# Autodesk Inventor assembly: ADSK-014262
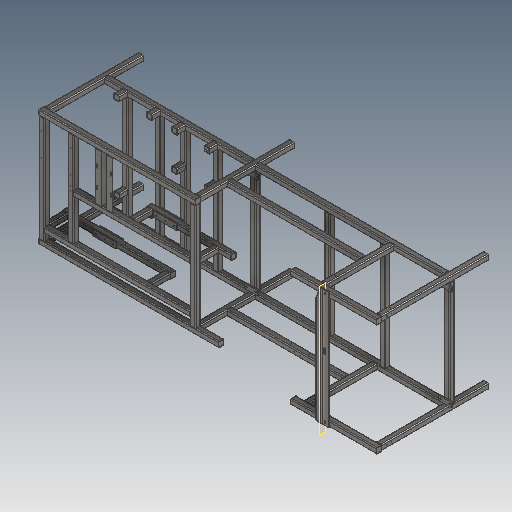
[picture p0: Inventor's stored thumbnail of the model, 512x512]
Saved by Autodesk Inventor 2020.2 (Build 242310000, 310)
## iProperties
Part Number: ADSK-014262
Description: Phantom-Baugruppe
Document SubType Name: Baugruppe
Designer: lutzd
Mass: 247578 g
Surface Area: 122547 cm^2
Volume: 31538.6 cm^3
Density: 7.85 g/cm^3
DocNumber: ADSK-014262
Folder: .
Dimensions: 1030x1037x3112,5 mm
Mass: 247,578 kg
_FrameDoc: Frame Assembly
_Version: 15.0.0
Title: Gestellbaugruppen
Author: lutzd
Revision Number: -
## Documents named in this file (57)
- D:\07 - DEMODATEN\OTX 2019 - Dataset - UPDATE - Dez2019\Designs\07-Packing machine\ADSK-014261\Frame\ADSK-014262.iam
- D:\07 - DEMODATEN\OTX 2019 - Dataset - UPDATE - Dez2019\Designs\07-Packing machine\ADSK-014261\Frame\ADSK-014267.ipt
- D:\07 - DEMODATEN\OTX 2019 - Dataset - UPDATE - Dez2019\Designs\07-Packing machine\ADSK-014261\Frame\ADSK-014265.ipt
- D:\07 - DEMODATEN\OTX 2019 - Dataset - UPDATE - Dez2019\Designs\07-Packing machine\ADSK-014261\Frame\ADSK-014264.ipt
- D:\07 - DEMODATEN\OTX 2019 - Dataset - UPDATE - Dez2019\Designs\07-Packing machine\ADSK-014261\Frame\ADSK-014263.ipt
- D:\07 - DEMODATEN\OTX 2019 - Dataset - UPDATE - Dez2019\Designs\07-Packing machine\ADSK-014261\Frame\ADSK-014280.ipt
- D:\07 - DEMODATEN\OTX 2019 - Dataset - UPDATE - Dez2019\Designs\07-Packing machine\ADSK-014261\Frame\ADSK-014279.ipt
- D:\07 - DEMODATEN\OTX 2019 - Dataset - UPDATE - Dez2019\Designs\07-Packing machine\ADSK-014261\Frame\ADSK-014278.ipt
- D:\07 - DEMODATEN\OTX 2019 - Dataset - UPDATE - Dez2019\Designs\07-Packing machine\ADSK-014261\Frame\ADSK-014276.ipt
- D:\07 - DEMODATEN\OTX 2019 - Dataset - UPDATE - Dez2019\Designs\07-Packing machine\ADSK-014261\Frame\ADSK-014275.ipt
- D:\07 - DEMODATEN\OTX 2019 - Dataset - UPDATE - Dez2019\Designs\07-Packing machine\ADSK-014261\Frame\ADSK-014274.ipt
- D:\07 - DEMODATEN\OTX 2019 - Dataset - UPDATE - Dez2019\Designs\07-Packing machine\ADSK-014261\Frame\ADSK-014273.ipt
- D:\07 - DEMODATEN\OTX 2019 - Dataset - UPDATE - Dez2019\Designs\07-Packing machine\ADSK-014261\Frame\ADSK-014272.ipt
- D:\07 - DEMODATEN\OTX 2019 - Dataset - UPDATE - Dez2019\Designs\07-Packing machine\ADSK-014261\Frame\ADSK-014271.ipt
- D:\07 - DEMODATEN\OTX 2019 - Dataset - UPDATE - Dez2019\Designs\07-Packing machine\ADSK-014261\Frame\ADSK-014270.ipt
- D:\07 - DEMODATEN\OTX 2019 - Dataset - UPDATE - Dez2019\Designs\07-Packing machine\ADSK-014261\Frame\ADSK-014269.ipt
- D:\07 - DEMODATEN\OTX 2019 - Dataset - UPDATE - Dez2019\Designs\07-Packing machine\ADSK-014261\Frame\ADSK-014268.ipt
- D:\07 - DEMODATEN\OTX 2019 - Dataset - UPDATE - Dez2019\Designs\07-Packing machine\ADSK-014261\Frame\ADSK-014304.ipt
- D:\07 - DEMODATEN\OTX 2019 - Dataset - UPDATE - Dez2019\Designs\07-Packing machine\ADSK-014261\Frame\ADSK-014303.ipt
- D:\07 - DEMODATEN\OTX 2019 - Dataset - UPDATE - Dez2019\Designs\07-Packing machine\ADSK-014261\Frame\ADSK-014302.ipt
- D:\07 - DEMODATEN\OTX 2019 - Dataset - UPDATE - Dez2019\Designs\07-Packing machine\ADSK-014261\Frame\ADSK-014301.ipt
- D:\07 - DEMODATEN\OTX 2019 - Dataset - UPDATE - Dez2019\Designs\07-Packing machine\ADSK-014261\Frame\ADSK-014300.ipt
- D:\07 - DEMODATEN\OTX 2019 - Dataset - UPDATE - Dez2019\Designs\07-Packing machine\ADSK-014261\Frame\ADSK-014299.ipt
- D:\07 - DEMODATEN\OTX 2019 - Dataset - UPDATE - Dez2019\Designs\07-Packing machine\ADSK-014261\Frame\ADSK-014298.ipt
- D:\07 - DEMODATEN\OTX 2019 - Dataset - UPDATE - Dez2019\Designs\07-Packing machine\ADSK-014261\Frame\ADSK-014297.ipt
- D:\07 - DEMODATEN\OTX 2019 - Dataset - UPDATE - Dez2019\Designs\07-Packing machine\ADSK-014261\Frame\ADSK-014296.ipt
- D:\07 - DEMODATEN\OTX 2019 - Dataset - UPDATE - Dez2019\Designs\07-Packing machine\ADSK-014261\Frame\ADSK-014295.ipt
- D:\07 - DEMODATEN\OTX 2019 - Dataset - UPDATE - Dez2019\Designs\07-Packing machine\ADSK-014261\Frame\ADSK-014294.ipt
- D:\07 - DEMODATEN\OTX 2019 - Dataset - UPDATE - Dez2019\Designs\07-Packing machine\ADSK-014261\Frame\ADSK-014293.ipt
- D:\07 - DEMODATEN\OTX 2019 - Dataset - UPDATE - Dez2019\Designs\07-Packing machine\ADSK-014261\Frame\ADSK-014292.ipt
- D:\07 - DEMODATEN\OTX 2019 - Dataset - UPDATE - Dez2019\Designs\07-Packing machine\ADSK-014261\Frame\ADSK-014291.ipt
- D:\07 - DEMODATEN\OTX 2019 - Dataset - UPDATE - Dez2019\Designs\07-Packing machine\ADSK-014261\Frame\ADSK-014290.ipt
- D:\07 - DEMODATEN\OTX 2019 - Dataset - UPDATE - Dez2019\Designs\07-Packing machine\ADSK-014261\Frame\ADSK-014289.ipt
- D:\07 - DEMODATEN\OTX 2019 - Dataset - UPDATE - Dez2019\Designs\07-Packing machine\ADSK-014261\Frame\ADSK-014288.ipt
- D:\07 - DEMODATEN\OTX 2019 - Dataset - UPDATE - Dez2019\Designs\07-Packing machine\ADSK-014261\Frame\ADSK-014287.ipt
- D:\07 - DEMODATEN\OTX 2019 - Dataset - UPDATE - Dez2019\Designs\07-Packing machine\ADSK-014261\Frame\ADSK-014286.ipt
- D:\07 - DEMODATEN\OTX 2019 - Dataset - UPDATE - Dez2019\Designs\07-Packing machine\ADSK-014261\Frame\ADSK-014285.ipt
- D:\07 - DEMODATEN\OTX 2019 - Dataset - UPDATE - Dez2019\Designs\07-Packing machine\ADSK-014261\Frame\ADSK-014284.ipt
- D:\07 - DEMODATEN\OTX 2019 - Dataset - UPDATE - Dez2019\Designs\07-Packing machine\ADSK-014261\Frame\ADSK-014283.ipt
- D:\07 - DEMODATEN\OTX 2019 - Dataset - UPDATE - Dez2019\Designs\07-Packing machine\ADSK-014261\Frame\ADSK-014282.ipt
- D:\07 - DEMODATEN\OTX 2019 - Dataset - UPDATE - Dez2019\Designs\07-Packing machine\ADSK-014261\Frame\ADSK-014281.ipt
- D:\07 - DEMODATEN\OTX 2019 - Dataset - UPDATE - Dez2019\Designs\07-Packing machine\ADSK-014261\Frame\ADSK-014306.ipt
- D:\07 - DEMODATEN\OTX 2019 - Dataset - UPDATE - Dez2019\Designs\07-Packing machine\ADSK-014261\Frame\ADSK-014305.ipt
- D:\07 - DEMODATEN\OTX 2019 - Dataset - UPDATE - Dez2019\Designs\07-Packing machine\Parts\ADSK-014314.ipt
- D:\07 - DEMODATEN\OTX 2019 - Dataset - UPDATE - Dez2019\Designs\07-Packing machine\Parts\ADSK-014311.ipt
- D:\07 - DEMODATEN\OTX 2019 - Dataset - UPDATE - Dez2019\Designs\07-Packing machine\Parts\ADSK-014310.ipt
- D:\07 - DEMODATEN\OTX 2019 - Dataset - UPDATE - Dez2019\Designs\07-Packing machine\ADSK-014261\Frame\ADSK-014318.ipt
- D:\07 - DEMODATEN\OTX 2019 - Dataset - UPDATE - Dez2019\Designs\07-Packing machine\ADSK-014261\Frame\ADSK-014327.ipt
- D:\07 - DEMODATEN\OTX 2019 - Dataset - UPDATE - Dez2019\Designs\07-Packing machine\ADSK-014261\Frame\ADSK-014328.ipt
- D:\07 - DEMODATEN\OTX 2019 - Dataset - UPDATE - Dez2019\Designs\07-Packing machine\ADSK-014261\Frame\ADSK-014332.ipt
- D:\07 - DEMODATEN\OTX 2019 - Dataset - UPDATE - Dez2019\Designs\07-Packing machine\ADSK-014261\Frame\ADSK-014331.ipt
- D:\07 - DEMODATEN\OTX 2019 - Dataset - UPDATE - Dez2019\Designs\07-Packing machine\ADSK-014261\Frame\ADSK-014330.ipt
- D:\07 - DEMODATEN\OTX 2019 - Dataset - UPDATE - Dez2019\Designs\07-Packing machine\ADSK-014261\Frame\ADSK-014333.ipt
- D:\07 - DEMODATEN\OTX 2019 - Dataset - UPDATE - Dez2019\Designs\07-Packing machine\ADSK-014261\Frame\ADSK-014329.ipt
- D:\07 - DEMODATEN\OTX 2019 - Dataset - UPDATE - Dez2019\Designs\07-Packing machine\ADSK-014261\Frame\ADSK-014335.ipt
- D:\07 - DEMODATEN\OTX 2019 - Dataset - UPDATE - Dez2019\Designs\07-Packing machine\ADSK-014261\Frame\_DS_FGM_DIN 50 x 50 x 5 1571498727313.ipt
- D:\07 - DEMODATEN\OTX 2019 - Dataset - UPDATE - Dez2019\Designs\07-Packing machine\ADSK-014261\Frame\Plate Gerundete Ecken (mm) 1571498778579.ipt
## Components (76 placed, 7 different names)
1. Gestellreferenzmodell
2. DIN 50 x 50 x 5:3
3. DIN 50 x 50 x 5:4
4. DIN 50 x 50 x 5:5
5. DIN 50 x 50 x 5:6
6. DIN 50 x 50 x 5:9
7. DIN 50 x 50 x 5:10
8. DIN 50 x 50 x 5:11
9. DIN 50 x 50 x 5:12
10. DIN 50 x 50 x 5:13
11. DIN 50 x 50 x 5:14
12. DIN 50 x 50 x 5:15
13. DIN 50 x 50 x 5:16
14. DIN 50 x 50 x 5:17
15. DIN 50 x 50 x 5:18
16. DIN 50 x 50 x 5:19
17. DIN 50 x 50 x 5:20
18. DIN 50 x 50 x 5:21
19. DIN 50 x 50 x 5:22
20. DIN 50 x 50 x 5:23
21. DIN 50 x 50 x 5:24
22. DIN 50 x 50 x 5:25
23. DIN 50 x 50 x 5:26
24. DIN 50 x 50 x 5:27
25. DIN 50 x 50 x 5:28
26. DIN 50 x 50 x 5:29
27. DIN 50 x 50 x 5:30
28. DIN 50 x 50 x 5:31
29. DIN 50 x 50 x 5:32
30. DIN 50 x 50 x 5:33
31. DIN 50 x 50 x 5:34
32. DIN 50 x 50 x 5:35
33. DIN 50 x 50 x 5:36
34. DIN 50 x 50 x 5:37
35. DIN 50 x 50 x 5:38
36. DIN 50 x 50 x 5:39
37. DIN 50 x 50 x 5:40
38. DIN 50 x 50 x 5:41
39. DIN L50x50x6:1
40. DIN L50x50x6:2
41. Gerundete Ecken (mm) 5 x 39,384472 x 39,384472:1
42. DIN 50 x 50 x 5:7
43. DIN 50 x 50 x 5:43
44. DIN 50 x 50 x 5:44
45. DIN 50 x 50 x 5:45
46. DIN 50 x 50 x 5:46
47. DIN L70x50x6:1
48. DIN 50 x 50 x 5:49
49. Gerundete Ecken (mm) 5 x 39,384472 x 39,384472:5
50. Gerundete Ecken (mm) 5 x 39,384472 x 39,384472:6
51. Gerundete Ecken (mm) 5 x 39,384472 x 39,384472:7
52. Gerundete Ecken (mm) 5 x 39,384472 x 39,384472:8
53. Gerundete Ecken (mm) 5 x 39,384472 x 39,384472:9
54. Gerundete Ecken (mm) 5 x 39,384472 x 39,384472:10
55. Gerundete Ecken (mm) 5 x 39,384472 x 39,384472:11
56. Gerundete Ecken (mm) 5 x 39,384472 x 39,384472:12
57. Gerundete Ecken (mm) 5 x 39,384472 x 39,384472:15
58. Gerundete Ecken (mm) 5 x 39,384472 x 39,384472:16
59. Gerundete Ecken (mm) 5 x 39,384472 x 39,384472:17
60. DIN 40 x 12:1
61. DIN 40 x 12:2
62. DIN 40 x 12:3
63. DIN 40 x 12:4
64. DIN 50 x 50 x 5:2
65. DIN 50 x 50 x 5:42
66. Gerundete Ecken (mm) 5 x 39,384472 x 39,384472:18
67. Gerundete Ecken (mm) 5 x 39,384472 x 39,384472:19
68. Gerundete Ecken (mm) 5 x 39,384472 x 39,384472:20
69. Gerundete Ecken (mm) 5 x 39,384472 x 39,384472:21
70. Gerundete Ecken (mm) 5 x 39,384472 x 39,384472:22
71. DIN 50 x 6:1
72. DIN 50 x 6:2
73. DIN 50 x 6:3
74. DIN 50 x 6:4
75. Gerundete Ecken (mm) 5 x 39,384472 x 39,384472:25
76. Gerundete Ecken (mm) 5 x 39,384472 x 39,384472:26
